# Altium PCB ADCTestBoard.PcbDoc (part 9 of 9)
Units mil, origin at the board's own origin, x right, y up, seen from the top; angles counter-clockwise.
Board outline 11022.62 x 9187 mil, 8 copper layers (TopLayer, InternalPlane1, InternalPlane2, InternalPlane3, InternalPlane4, InternalPlane5, MidLayer1, BottomLayer), stack 103.8 mil thick; 1282 components, 637 nets, 4473 pads, 1306 vias.
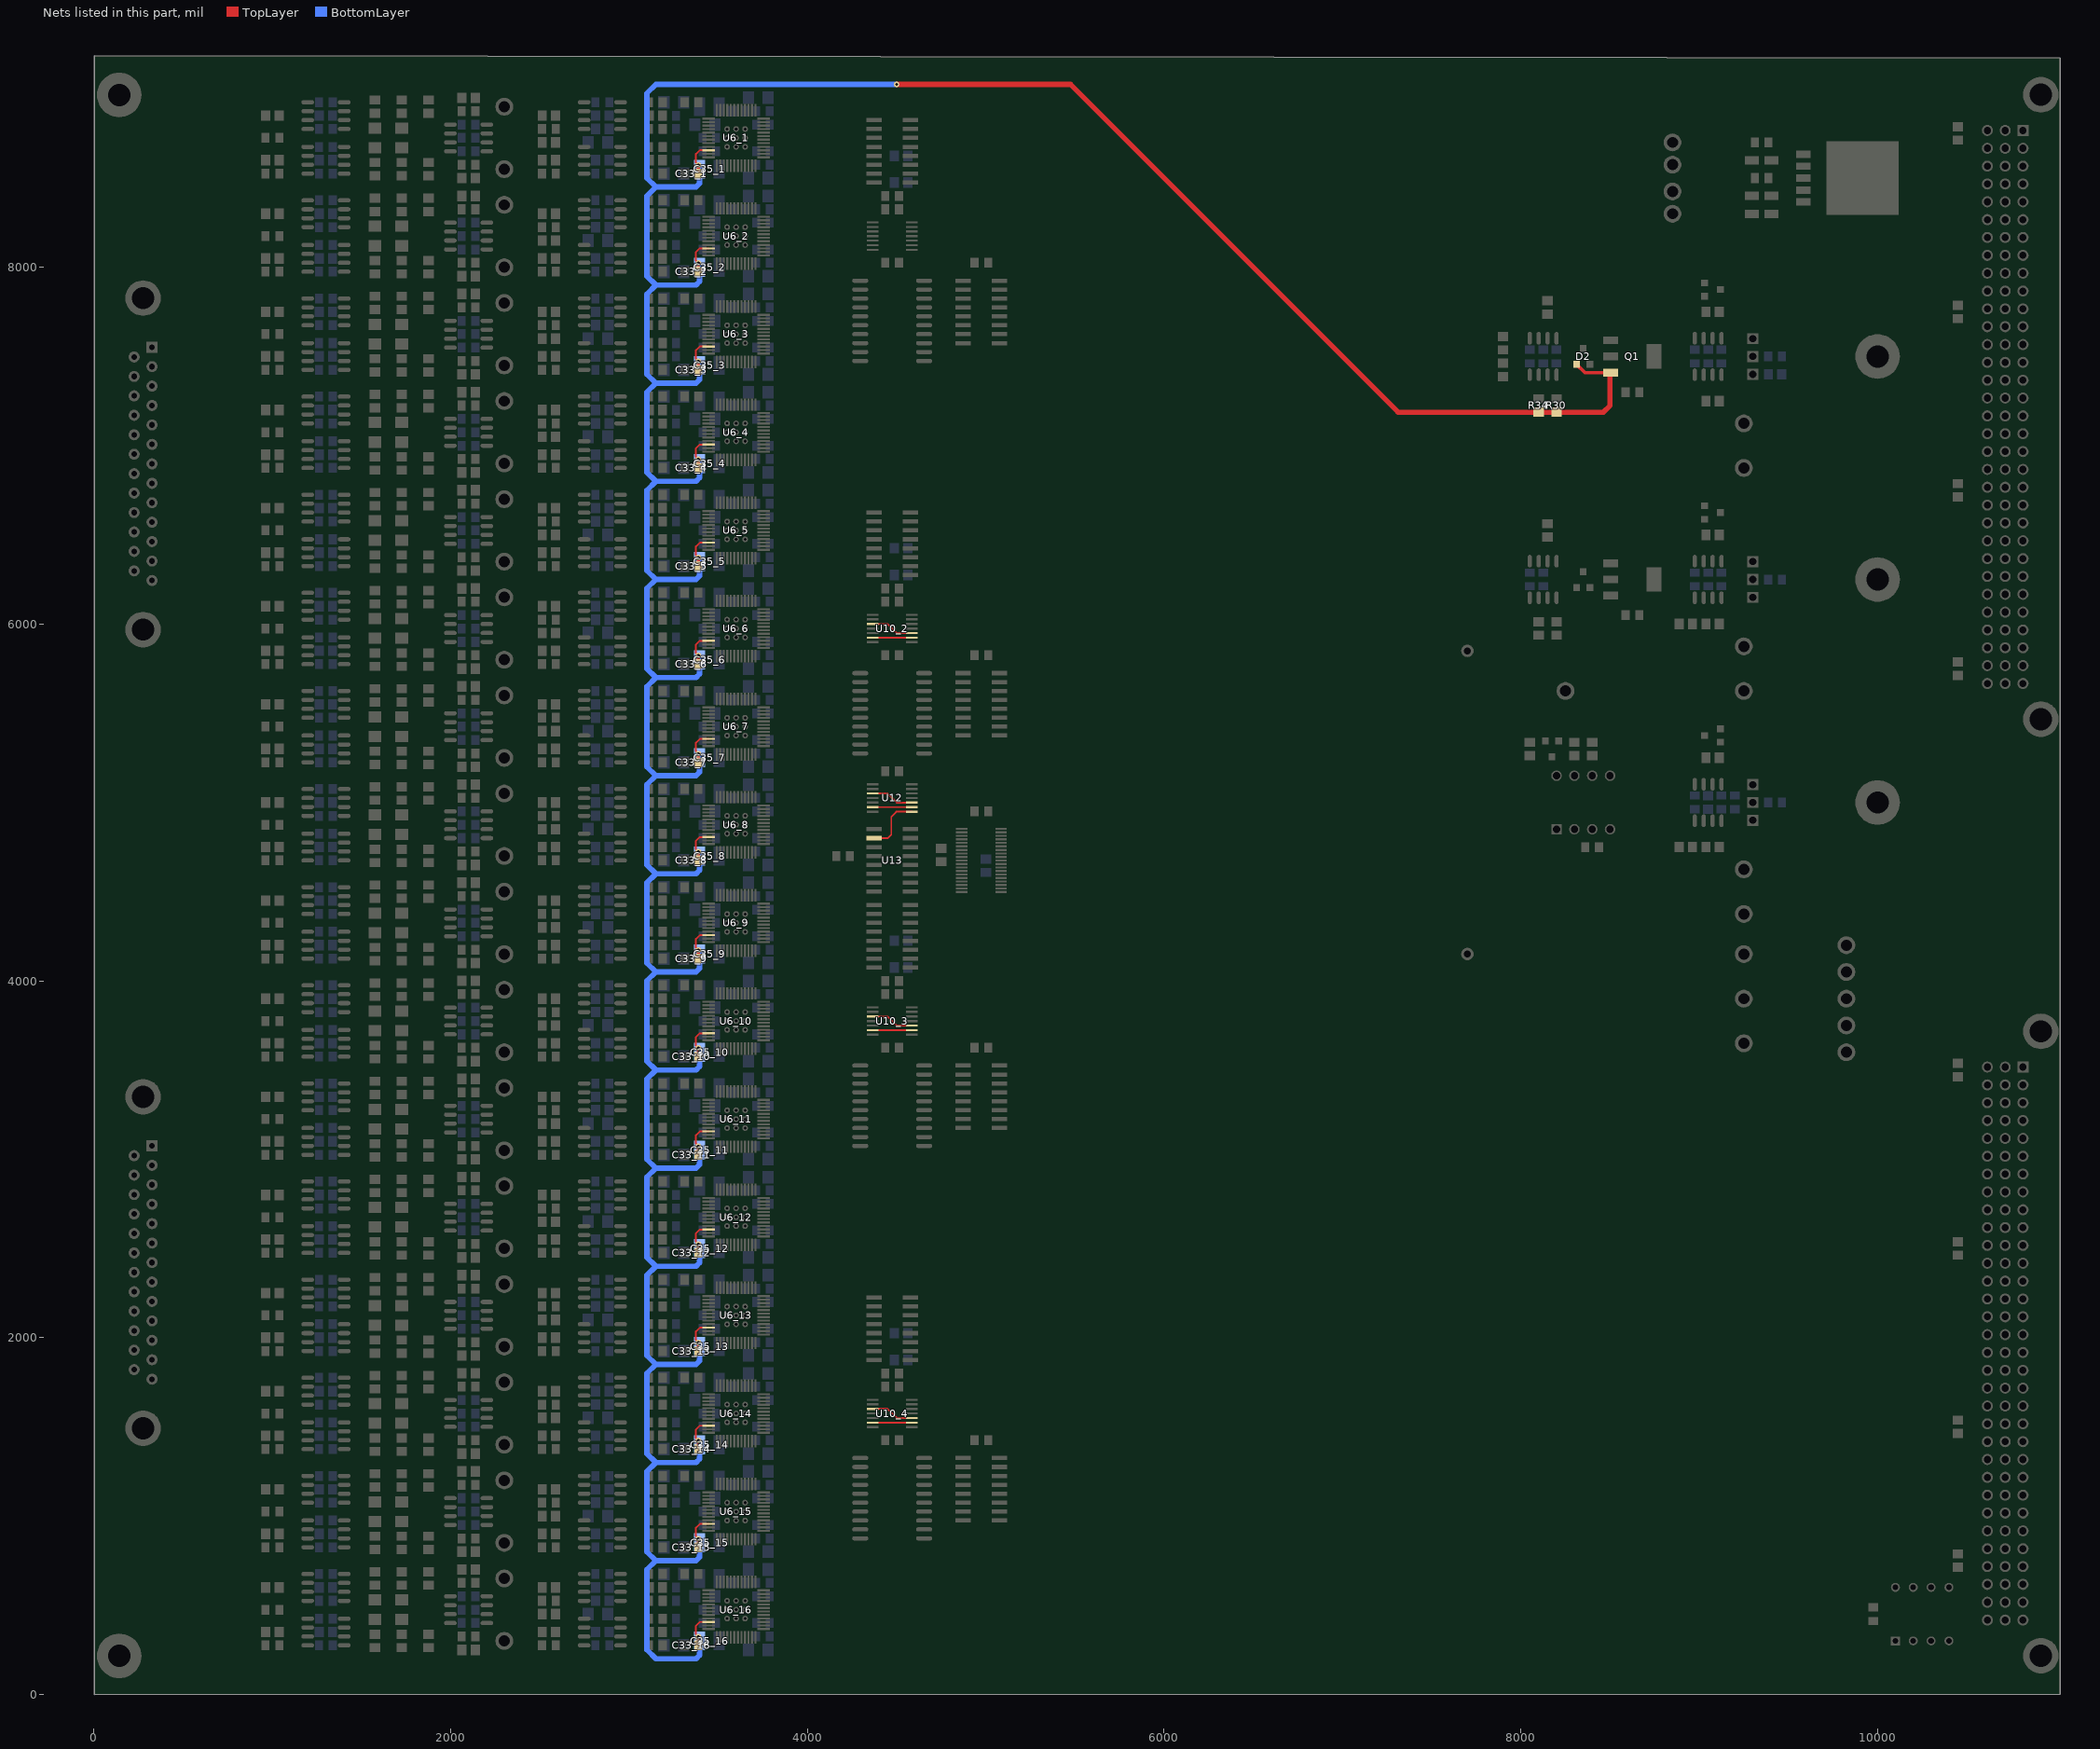
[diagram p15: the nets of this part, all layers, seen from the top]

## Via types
v1: diameter 32, hole 16, TopLayer to BottomLayer, 1306 vias

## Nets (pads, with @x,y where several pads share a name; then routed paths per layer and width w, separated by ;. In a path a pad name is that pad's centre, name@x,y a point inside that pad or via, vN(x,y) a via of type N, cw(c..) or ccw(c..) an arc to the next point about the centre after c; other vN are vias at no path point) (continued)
NetU10_2_3: U10_2.3 U10_2.10 | length 239.7
  TopLayer w10: U10_2.3@4365.75,6000.59 4449.41,6000.59 4500.59,5949.41 U10_2.10@4584.25,5949.41
NetU10_2_6: U10_2.6 U10_2.9 | length 218.5
  TopLayer w10: U10_2.6@4365.75,5923.82 U10_2.9@4584.25,5923.82
NetU10_3_3: U10_3.3 U10_3.10 | length 239.7
  TopLayer w10: U10_3.3@4365.75,3800.59 4449.41,3800.59 4500.59,3749.41 U10_3.10@4584.25,3749.41
NetU10_3_6: U10_3.6 U10_3.9 | length 218.5
  TopLayer w10: U10_3.6@4365.75,3723.82 U10_3.9@4584.25,3723.82
NetU10_4_3: U10_4.3 U10_4.10 | length 239.7
  TopLayer w10: U10_4.3@4365.75,1600.59 4449.41,1600.59 4500.59,1549.41 U10_4.10@4584.25,1549.41
NetU10_4_6: U10_4.6 U10_4.9 | length 218.5
  TopLayer w10: U10_4.6@4365.75,1523.82 U10_4.9@4584.25,1523.82
NetU12_3: U12.3 U12.10 | length 239.7
  TopLayer w10: U12.3@4365.75,5050.59 4449.41,5050.59 4500.59,4999.41 U12.10@4584.25,4999.41
NetU12_6: U12.6 U12.9 | length 218.5
  TopLayer w10: U12.6@4365.75,4973.82 U12.9@4584.25,4973.82
NetU12_8: U12.8 U13.2 | length 331.6
  TopLayer w10: U13.2@4372.64,4800 4450,4800 4470,4820 4470,4920 4498.23,4948.23 U12.8@4584.25,4948.23
REF: C33_1.2 C33_2.2 C33_3.2 C33_4.2 C33_5.2 C33_6.2 C33_7.2 C33_8.2 C33_9.2 C33_10.2 C33_11.2 C33_12.2 C33_13.2 C33_14.2 C33_15.2 C33_16.2 C35_1.1 C35_2.1 C35_3.1 C35_4.1 C35_5.1 C35_6.1 C35_7.1 C35_8.1 C35_9.1 C35_10.1 C35_11.1 C35_12.1 C35_13.1 C35_14.1 C35_15.1 C35_16.1 D2.1 Q1.3 R30.2 R34.1 U6_1.46 U6_2.46 U6_3.46 U6_4.46 U6_5.46 U6_6.46 U6_7.46 U6_8.46 U6_9.46 U6_10.46 U6_11.46 U6_12.46 U6_13.46 U6_14.46 U6_15.46 U6_16.46 | length 24449.8
  TopLayer w10: v1(3388.39,323.39) 3375,336.77 3375,385 3396.1,406.1 U6_16.46@3445,406.1 ; v1(3388.39,873.39) 3375,886.77 3375,935 3396.1,956.1 U6_15.46@3445,956.1 ; v1(3388.39,1423.39) 3375,1436.77 3375,1485 3396.1,1506.1 U6_14.46@3445,1506.1 ; v1(3388.39,1973.39) 3375,1986.77 3375,2035 3396.1,2056.1 U6_13.46@3445,2056.1 ; v1(3388.39,2523.39) 3375,2536.77 3375,2585 3396.1,2606.1 U6_12.46@3445,2606.1 ; v1(3388.39,3073.39) 3375,3086.77 3375,3135 3396.1,3156.1 U6_11.46@3445,3156.1 ; v1(3388.39,3623.39) 3375,3636.77 3375,3685 3396.1,3706.1 U6_10.46@3445,3706.1 ; v1(3388.39,4173.39) 3375,4186.77 3375,4235 3396.1,4256.1 U6_9.46@3445,4256.1 ; v1(3388.39,4723.39) 3375,4736.77 3375,4785 3396.1,4806.1 U6_8.46@3445,4806.1 ; v1(3388.39,5273.39) 3375,5286.77 3375,5335 3396.1,5356.1 U6_7.46@3445,5356.1 ; v1(3388.39,5823.39) 3375,5836.77 3375,5885 3396.1,5906.1 U6_6.46@3445,5906.1 ; v1(3388.39,6373.39) 3375,6386.77 3375,6435 3396.1,6456.1 U6_5.46@3445,6456.1 ; v1(3388.39,6923.39) 3375,6936.77 3375,6985 3396.1,7006.1 U6_4.46@3445,7006.1 ; v1(3388.39,7473.39) 3375,7486.77 3375,7535 3396.1,7556.1 U6_3.46@3445,7556.1 ; v1(3388.39,8023.39) 3375,8036.77 3375,8085 3396.1,8106.1 U6_2.46@3445,8106.1 ; v1(3388.39,8573.39) 3375,8586.77 3375,8635 3396.1,8656.1 U6_1.46@3445,8656.1
  TopLayer w20: C33_16.2@3388.39,275 v1(3388.39,323.39) ; C33_15.2@3388.39,825 v1(3388.39,873.39) ; C33_14.2@3388.39,1375 v1(3388.39,1423.39) ; C33_13.2@3388.39,1925 v1(3388.39,1973.39) ; C33_12.2@3388.39,2475 v1(3388.39,2523.39) ; C33_11.2@3388.39,3025 v1(3388.39,3073.39) ; C33_10.2@3388.39,3575 v1(3388.39,3623.39) ; C33_9.2@3388.39,4125 v1(3388.39,4173.39) ; C33_8.2@3388.39,4675 v1(3388.39,4723.39) ; C33_7.2@3388.39,5225 v1(3388.39,5273.39) ; C33_6.2@3388.39,5775 v1(3388.39,5823.39) ; C33_5.2@3388.39,6325 v1(3388.39,6373.39) ; C33_4.2@3388.39,6875 v1(3388.39,6923.39) ; C33_3.2@3388.39,7425 v1(3388.39,7473.39) ; C33_2.2@3388.39,7975 v1(3388.39,8023.39) ; C33_1.2@3388.39,8525 v1(3388.39,8573.39) ; D2.1@8312.6,7455.71 8358.86,7409.45 Q1.3@8502.95,7409.45
  TopLayer w30: v1(4500,9025) 5475,9025 7312.4,7187.6 R30.2@8200,7187.6 8462.6,7187.6 8500,7225 8500,7406.5 Q1.3@8502.95,7409.45
  BottomLayer w30: C35_16.1@3394.88,300 3394.88,219.88 3375,200 3150,200 3100,250 3100,700 3150,750 ; C35_15.1@3394.88,850 3394.88,769.88 3375,750 3150,750 ; C35_14.1@3394.88,1400 3394.88,1319.88 3375,1300 3150,1300 ; C35_13.1@3394.88,1950 3394.88,1869.88 3375,1850 3150,1850 ; C35_12.1@3394.88,2500 3394.88,2419.88 3375,2400 3150,2400 ; C35_11.1@3394.88,3050 3394.88,2969.88 3375,2950 3150,2950 ; C35_10.1@3394.88,3600 3394.88,3519.88 3375,3500 3150,3500 ; C35_9.1@3394.88,4150 3394.88,4069.88 3375,4050 3150,4050 ; C35_8.1@3394.88,4700 3394.88,4619.88 3375,4600 3150,4600 ; C35_7.1@3394.88,5250 3394.88,5169.88 3375,5150 3150,5150 ; C35_6.1@3394.88,5800 3394.88,5719.88 3375,5700 3150,5700 ; C35_5.1@3394.88,6350 3394.88,6269.88 3375,6250 3150,6250 ; C35_4.1@3394.88,6900 3394.88,6819.88 3375,6800 3150,6800 ; C35_3.1@3394.88,7450 3394.88,7369.88 3375,7350 3150,7350 ; C35_2.1@3394.88,8000 3394.88,7919.88 3375,7900 3150,7900 ; C35_1.1@3394.88,8550 3394.88,8469.88 3375,8450 3150,8450 ; v1(4500,9025) 3150,9025 3100,8975 3100,8500 3150,8450 ; 3150,750 3100,800 3100,1250 3150,1300 ; 3150,1300 3100,1350 3100,1800 3150,1850 ; 3150,1850 3100,1900 3100,2350 3150,2400 ; 3150,2400 3100,2450 3100,2900 3150,2950 ; 3150,2950 3100,3000 3100,3450 3150,3500 ; 3150,3500 3100,3550 3100,4000 3150,4050 ; 3150,4050 3100,4100 3100,4550 3150,4600 ; 3150,4600 3100,4650 3100,5100 3150,5150 ; 3150,5150 3100,5200 3100,5650 3150,5700 ; 3150,5700 3100,5750 3100,6200 3150,6250 ; 3150,6250 3100,6300 3100,6750 3150,6800 ; 3150,6800 3100,6850 3100,7300 3150,7350 ; 3150,7350 3100,7400 3100,7850 3150,7900 ; 3150,7900 3100,7950 3100,8400 3150,8450
pads on no net: D1.2 D2.2 D3.2 D4.2 D5.2 D6.2 J1.12 J1.13 J1.25 J2.12 J2.13 J2.25 P1.0 P1.11A P1.12A P1.14A P1.15A P1.15C P1.16C P1.17A P1.17C P1.18A P1.18C P1.19C P1.20A P1.20C P1.21A P1.21C P1.22C P1.23A P1.23C P1.24A P1.24C P1.25A P1.26A P1.27A P1.28A P1.29A P1.30A P1.31A P1.32A P2.0 P2.13C P2.14C P2.15C P2.16C P2.17C P2.18C P2.19C P2.20C P2.21C P2.22C P2.23C P2.24C P2.25C Q2.0 Q3.0 Q4.0 U1_1.1 U1_1.8 U1_2.1 U1_2.8 U1_3.1 U1_3.8 U1_4.1 U1_4.8 U1_5.1 U1_5.8 U1_6.1 U1_6.8 U1_7.1 U1_7.8 U1_8.1 U1_8.8 U1_9.1 U1_9.8 U1_10.1 U1_10.8 U1_11.1 U1_11.8 U1_12.1 U1_12.8 U1_13.1 U1_13.8 U1_14.1 U1_14.8 U1_15.1 U1_15.8 U1_16.1 U1_16.8 U2_1.1 U2_1.8 U2_2.1 U2_2.8 U2_3.1 U2_3.8 U2_4.1 U2_4.8 U2_5.1 U2_5.8 U2_6.1 U2_6.8 U2_7.1 U2_7.8 U2_8.1 U2_8.8 U2_9.1 U2_9.8 U2_10.1 U2_10.8 U2_11.1 U2_11.8 U2_12.1 U2_12.8 U2_13.1 U2_13.8 U2_14.1 U2_14.8 U2_15.1 U2_15.8 U2_16.1 U2_16.8 U3_1.1 U3_1.8 U3_2.1 U3_2.8 U3_3.1 U3_3.8 U3_4.1 U3_4.8 U3_5.1 U3_5.8 U3_6.1 U3_6.8 U3_7.1 U3_7.8 U3_8.1 U3_8.8 U3_9.1 U3_9.8 U3_10.1 U3_10.8 U3_11.1 U3_11.8 U3_12.1 U3_12.8 U3_13.1 U3_13.8 U3_14.1 U3_14.8 U3_15.1 U3_15.8 U3_16.1 U3_16.8 U4_1.1 U4_1.8 U4_2.1 U4_2.8 U4_3.1 U4_3.8 U4_4.1 U4_4.8 U4_5.1 U4_5.8 U4_6.1 U4_6.8 U4_7.1 U4_7.8 U4_8.1 U4_8.8 U4_9.1 U4_9.8 U4_10.1 U4_10.8 U4_11.1 U4_11.8 U4_12.1 U4_12.8 U4_13.1 U4_13.8 U4_14.1 U4_14.8 U4_15.1 U4_15.8 U4_16.1 U4_16.8 U5_1.1 U5_1.8 U5_2.1 U5_2.8 U5_3.1 U5_3.8 U5_4.1 U5_4.8 U5_5.1 U5_5.8 U5_6.1 U5_6.8 U5_7.1 U5_7.8 U5_8.1 U5_8.8 U5_9.1 U5_9.8 U5_10.1 U5_10.8 U5_11.1 U5_11.8 U5_12.1 U5_12.8 U5_13.1 U5_13.8 U5_14.1 U5_14.8 U5_15.1 U5_15.8 U5_16.1 U5_16.8 U6_1.8 U6_1.9 U6_1.10 U6_1.11 U6_1.12 U6_1.23 U6_1.24 U6_1.25 U6_1.26 U6_1.27 U6_1.28 U6_1.45 U6_2.8 U6_2.9 U6_2.10 U6_2.11 U6_2.12 U6_2.23 U6_2.24 U6_2.25 U6_2.26 U6_2.27 U6_2.28 U6_2.45 U6_3.8 U6_3.9 U6_3.10 U6_3.11 U6_3.12 U6_3.23 U6_3.24 U6_3.25 U6_3.26 U6_3.27 U6_3.28 U6_3.45 U6_4.8 U6_4.9 U6_4.10 U6_4.11 U6_4.12 U6_4.23 U6_4.24 U6_4.25 U6_4.26 U6_4.27 U6_4.28 U6_4.45 U6_5.8 U6_5.9 U6_5.10 U6_5.11 U6_5.12 U6_5.23 U6_5.24 U6_5.25 U6_5.26 U6_5.27 U6_5.28 U6_5.45 U6_6.8 U6_6.9 U6_6.10 U6_6.11 U6_6.12 U6_6.23 U6_6.24 U6_6.25 U6_6.26 U6_6.27 U6_6.28 U6_6.45 U6_7.8 U6_7.9 U6_7.10 U6_7.11 U6_7.12 U6_7.23 U6_7.24 U6_7.25 U6_7.26 U6_7.27 U6_7.28 U6_7.45 U6_8.8 U6_8.9 U6_8.10 U6_8.11 U6_8.12 U6_8.23 U6_8.24 U6_8.25 U6_8.26 U6_8.27 U6_8.28 U6_8.45 U6_9.8 U6_9.9 U6_9.10 U6_9.11 U6_9.12 U6_9.23 U6_9.24 U6_9.25 U6_9.26 U6_9.27 U6_9.28 U6_9.45 U6_10.8 U6_10.9 U6_10.10 U6_10.11 U6_10.12 U6_10.23 U6_10.24 U6_10.25 U6_10.26 U6_10.27 U6_10.28 U6_10.45 U6_11.8 U6_11.9 U6_11.10 U6_11.11 U6_11.12 U6_11.23 U6_11.24 U6_11.25 U6_11.26 U6_11.27 U6_11.28 U6_11.45 U6_12.8 U6_12.9 U6_12.10 U6_12.11 U6_12.12 U6_12.23 U6_12.24 U6_12.25 U6_12.26 U6_12.27 U6_12.28 U6_12.45 U6_13.8 U6_13.9 U6_13.10 U6_13.11 U6_13.12 U6_13.23 U6_13.24 U6_13.25 U6_13.26 U6_13.27 U6_13.28 U6_13.45 U6_14.8 U6_14.9 U6_14.10 U6_14.11 U6_14.12 U6_14.23 U6_14.24 U6_14.25 U6_14.26 U6_14.27 U6_14.28 U6_14.45 U6_15.8 U6_15.9 U6_15.10 U6_15.11 U6_15.12 U6_15.23 U6_15.24 U6_15.25 U6_15.26 U6_15.27 U6_15.28 U6_15.45 U6_16.8 U6_16.9 U6_16.10 U6_16.11 U6_16.12 U6_16.23 U6_16.24 U6_16.25 U6_16.26 U6_16.27 U6_16.28 U6_16.45 U7_1.5 U7_1.6 U7_1.7 U7_1.8 U7_1.10 U7_1.11 U7_2.5 U7_2.6 U7_2.7 U7_2.8 U7_2.10 U7_2.11 U7_3.5 U7_3.6 U7_3.7 U7_3.8 U7_3.10 U7_3.11 U7_4.5 U7_4.6 U7_4.7 U7_4.8 U7_4.10 U7_4.11 U8_1.12 U8_1.13 U8_1.14 U8_1.15 U8_2.12 U8_2.13 U8_2.14 U8_2.15 U8_3.12 U8_3.13 U8_3.14 U8_3.15 U8_4.12 U8_4.13 U8_4.14 U8_4.15 U10_1.11 U10_2.11 U10_3.11 U10_4.11 U11.4 U11.15 U11.16 U11.24 U11.29 U11.34 U12.11 U13.9 U13.10 U13.11 U13.12 U13.13 U13.14 U15.1 U15.8 U16.1 U16.5 U16.8 U17.1 U17.3 U17.5 U17.7 U17.8 U18.1 U18.8 U19.1 U19.8 U20.1 U20.8 U21.6

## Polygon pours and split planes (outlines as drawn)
GND on InternalPlane1 (split plane): 10923.14,9072.86 10923.14,4724.41 10923.14,100.47 101.48,99.49 101.48,9085.4
+5V on InternalPlane2 (split plane): 10923.14,9072.86 10923.14,4724.41 10923.14,100.47 101.48,99.49 101.48,9085.4
+15V on InternalPlane3 (split plane): 10923.14,9072.86 10923.14,4724.41 10923.14,100.47 101.48,99.49 101.48,9085.4
-15V on InternalPlane4 (split plane): 10923.14,9072.86 10923.14,4724.41 10923.14,100.47 101.48,99.49 101.48,9085.4
+3.3V on InternalPlane5 (split plane): 10923.14,9072.86 10923.14,4724.41 10923.14,100.47 101.48,99.49 101.48,9085.4
+5VR on BottomLayer "BottomLayer-+5VR" (solid, remove dead copper, shelved, pour order 1001): 9250,8000 7800,8000 7800,4500 9300,4500 9300,8000
GND on MidLayer1 "MidLayer1-GND" (solid, remove dead copper, shelved, pour order 1000): 100,125 3525,125 3525,9050 100,9050
DGND on MidLayer1 "MidLayer1-DGND" (solid, remove dead copper, shelved, pour order 1001): 3550,125 3550,9050 10925,9050 10925,125
DV1 on TopLayer "TopLayer-DV1" (solid, remove dead copper, shelved, pour order 1000): 10750,8850 10750,8200 10525,8200 10525,8540 8775,8540 8775,8850

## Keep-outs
KeepOutLayer:
  lines w7.99: 240.98,117.01 10815.39,117.01 ; 240.98,9067.01 10815.39,9067.01
  lines w8: 241,117 241,317 66,317 66,3867 66,5617 66,8867 241,8867 241,9067 ; 10815.41,117 10815.41,317 10965.41,317 10965.41,3617 10815.41,3617 10815.41,3817 10965.41,3817 10965.41,5367 10815.41,5367 10815.41,5567 10965.41,5567 10965.41,8867 10815.41,8867 10815.41,9067
Mechanical2:
  lines w10: -220,320 -220,8867 ; -120,320 -120,8866 -119,8867

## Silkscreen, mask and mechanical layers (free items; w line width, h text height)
TopOverlay:
  circle w10: c141,216 r112.5
  circle w10: c141,8966 r112.5
  rectangle: 8800,145 9720,800
  rectangle: 9250,840 9720,1100
  lines w9.84: 9024,1419 ccw(c9144,1419) 9144,1299 ; 9044,1419 ccw(c9144,1419) 9144,1319 ; 9064,1419 ccw(c9144,1419) 9144,1339 ; 9084,1419 ccw(c9144,1419) 9144,1359
  lines w10: 500,200 3950,200 ; 500,750 3950,750 ; 500,1300 3950,1300 ; 500,1850 3950,1850 ; 500,2400 3950,2400 ; 500,2950 3950,2950 ; 500,3500 3950,3500 ; 500,4050 3950,4050 ; 500,4600 3950,4600 ; 500,5150 3950,5150 ; 500,5700 3950,5700 ; 500,6250 3950,6250 ; 500,6800 3950,6800 ; 500,7350 3950,7350 ; 500,7900 3950,7900 ; 500,8450 3950,8450
  text "Ch. 1" at 500,8500 h60
  text "Ch. 2" at 500,7950 h60
  text "Ch. 3" at 500,7400 h60
  text "Ch. 4" at 500,6850 h60
  text "Ch. 5" at 500,6300 h60
  text "Ch. 6" at 500,5750 h60
  text "Ch. 7" at 500,5200 h60
  text "Ch. 8" at 500,4650 h60
  text "Ch. 9" at 500,4100 h60
  text "Ch. 10" at 500,3550 h60
  text "Ch. 11" at 500,3000 h60
  text "Ch. 12" at 500,2450 h60
  text "Ch. 13" at 500,1900 h60
  text "Ch. 14" at 500,1350 h60
  text "LIGO" at 8800,1250 h72
  text "PROJECT" at 9200,1250 h60
  text "ADC Test Board" at 8800,1150 h60
  text "D060535" at 8800,1050 h60
  text "Rev A-" at 8800,950 h60
  text "S/N:" at 8800,850 h60
  text "Ch. 15" at 500,800 h60
  text "Ch. 16" at 500,250 h60
TopPaste:
  text ".GTP" at 11511.81,7725.2 h90
BottomPaste:
  text ".GBP" at 11511.81,7725.2 h90
TopSolder:
  text ".GTS" at 11511.81,7725.2 h90
BottomSolder:
  text ".GBS" at 11511.81,7725.2 h90
Mechanical1:
  lines w20: 0.98,-0.98 0.98,9174.21 11024.41,9174.21 11024.41,-0.98 0.98,-0.98
Mechanical2:
  lines w10: -220,320 -520,320 -520,270 -1520,270 -1520,320 -1620,320 -1620,20 -720,-380 -720,-680 -120,-680 -120,-280 40,-280 40,100 240,100 240,320 -120,320 ; -220,8867 -519,8867 -519,8917 -1519,8917 -1519,8867 -1619,8867 -1619,9167 -719,9567 -719,9867 -119,9867 -119,9467 41,9467 41,9087 240,9087 240,8870 -119,8867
